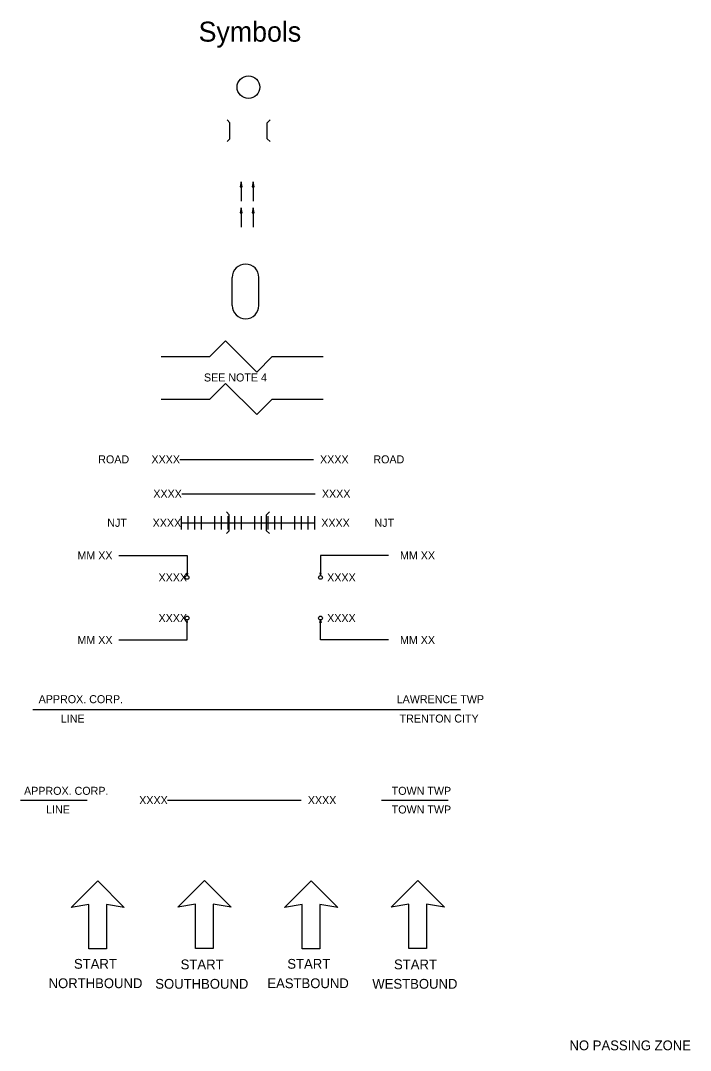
# Model space of a CAD drawing. Extents: x -6359 to 1641, y 3001 to 24737.
# Drawn here: x -4123 to 900, y 3001 to 10724 of the extents above; entities that cross this region are included whole.
import ezdxf

# ---------------------------------------------------------------- set-up
doc = ezdxf.new("R2010")
doc.units = 0
doc.layers.add('_Notes', color=7, linetype='Continuous')

msp = doc.modelspace()

# ---------------------------------------------------------------- linework, layer by layer
at = {"layer": '_Notes'}
for p, q in [((-2553.2, 9957.4), (-2574.4, 9978.6)), ((-2273.2, 9957.4), (-2252, 9978.6)), ((-2553.2, 9837.4), (-2553.2, 9957.4)), ((-2273.2, 9837.4), (-2273.2, 9957.4)), ((-2574.4, 9816.1), (-2553.2, 9837.4)), ((-2252, 9816.1), (-2273.2, 9837.4)), ((-2469.7, 9515.4), (-2469.7, 9370.5)), ((-2379, 9515.4), (-2379, 9370.5)), ((-2469.7, 9319.3), (-2469.7, 9174.4)), ((-2379, 9319.3), (-2379, 9174.4)), ((-2536, 8587.7), (-2536, 8797.7)), ((-2336, 8587.7), (-2336, 8797.7)), ((-2703.4, 8205.1), (-2586.6, 8321.9)), ((-2586.6, 8321.9), (-2352.8, 8088.2)), ((-3068.9, 8205.1), (-2703.4, 8205.1)), ((-2352.8, 8088.2), (-2235.8, 8205.1)), ((-2235.8, 8205.1), (-1853.9, 8205.1)), ((-2703.4, 7885.7), (-2586.6, 8002.5)), ((-2586.6, 8002.5), (-2352.8, 7768.8)), ((-3068.9, 7885.7), (-2703.4, 7885.7)), ((-2352.8, 7768.8), (-2235.8, 7885.7)), ((-2235.8, 7885.7), (-1853.9, 7885.7)), ((-2928.6, 7433.2), (-2428.2, 7433.2)), ((-2428.2, 7433.2), (-1927.7, 7433.2)), ((-2914.6, 7175.7), (-2414.2, 7175.7)), ((-2414.2, 7175.7), (-1913.7, 7175.7)), ((-2559.1, 7017.3), (-2580.3, 7038.5)), ((-2279.1, 7017.3), (-2257.8, 7038.5)), ((-2919.5, 7007.1), (-2919.5, 6907.1)), ((-2919.5, 6957.1), (-2419.1, 6957.3)), ((-2869.5, 7007.1), (-2869.5, 6907.1)), ((-2819.5, 7007.1), (-2819.5, 6907.1)), ((-2769.5, 7007.1), (-2769.5, 6907.1)), ((-2669.5, 7007.1), (-2669.5, 6907.1)), ((-2619.5, 7007.1), (-2619.5, 6907.1)), ((-2569.5, 7007.1), (-2569.5, 6907.1)), ((-2559.1, 6897.3), (-2559.1, 7017.3)), ((-2519.5, 7007.1), (-2519.5, 6907.1)), ((-2469.5, 7007.1), (-2469.5, 6907.1)), ((-2419.1, 6957.3), (-1918.6, 6957.3)), ((-2369.1, 7007.3), (-2369.1, 6907.3)), ((-2319.1, 7007.3), (-2319.1, 6907.3)), ((-2279.1, 6897.3), (-2279.1, 7017.3)), ((-2269.1, 7007.3), (-2269.1, 6907.3)), ((-2219.1, 7007.3), (-2219.1, 6907.3)), ((-2169.1, 7007.3), (-2169.1, 6907.3)), ((-2069.1, 7007.3), (-2069.1, 6907.3)), ((-2019.1, 7007.3), (-2019.1, 6907.3)), ((-1969.1, 7007.3), (-1969.1, 6907.3)), ((-1919.1, 7007.3), (-1919.1, 6907.3)), ((-2580.3, 6876.1), (-2559.1, 6897.3)), ((-2257.8, 6876.1), (-2279.1, 6897.3)), ((-3386.4, 6712), (-2875.3, 6712)), ((-2875.3, 6712), (-2875.3, 6561.8)), ((-1874.4, 6712), (-1874.4, 6561.8)), ((-1363.3, 6712), (-1874.4, 6712)), ((-2875.3, 6079.3), (-2875.3, 6229.4)), ((-1874.4, 6079.3), (-1874.4, 6229.4)), ((-3386.4, 6079.3), (-2875.3, 6079.3)), ((-1363.3, 6079.3), (-1874.4, 6079.3)), ((-4031.2, 5556.5), (-3531.2, 5556.5)), ((-3531.2, 5556.5), (-1324.5, 5556.5)), ((-1324.5, 5556.5), (-824.5, 5556.5)), ((-4123.3, 4877.6), (-3623.3, 4877.6)), ((-3020.4, 4877.6), (-2519.9, 4877.6)), ((-2519.9, 4877.6), (-2019.4, 4877.6)), ((-1416.5, 4877.6), (-916.5, 4877.6)), ((-3744.3, 4072), (-3544.8, 4271.5)), ((-3544.8, 4271.5), (-3345.4, 4072)), ((-2944.3, 4076.3), (-2744.8, 4275.8)), ((-2744.8, 4275.8), (-2545.4, 4076.3)), ((-2144.3, 4072), (-1944.8, 4271.5)), ((-1944.8, 4271.5), (-1745.4, 4072)), ((-1344.3, 4076.3), (-1144.8, 4275.8)), ((-1144.8, 4275.8), (-945.4, 4076.3)), ((-3611.3, 4094.2), (-3744.3, 4072)), ((-3611.3, 3761.7), (-3611.3, 4094.2)), ((-3345.4, 4072), (-3478.3, 4094.2)), ((-3478.3, 4094.2), (-3478.3, 3761.7)), ((-2811.3, 4098.5), (-2944.3, 4076.3)), ((-2811.3, 3766), (-2811.3, 4098.5)), ((-2545.4, 4076.3), (-2678.3, 4098.5)), ((-2678.3, 4098.5), (-2678.3, 3766)), ((-2011.3, 4094.2), (-2144.3, 4072)), ((-2011.3, 3761.7), (-2011.3, 4094.2)), ((-1745.4, 4072), (-1878.3, 4094.2)), ((-1878.3, 4094.2), (-1878.3, 3761.7)), ((-1211.3, 4098.5), (-1344.3, 4076.3)), ((-1211.3, 3766), (-1211.3, 4098.5)), ((-945.4, 4076.3), (-1078.3, 4098.5)), ((-1078.3, 4098.5), (-1078.3, 3766)), ((-3478.3, 3761.7), (-3611.3, 3761.7)), ((-2678.3, 3766), (-2811.3, 3766)), ((-1878.3, 3761.7), (-2011.3, 3761.7)), ((-1078.3, 3766), (-1211.3, 3766))]:
    msp.add_line(p, q, dxfattribs=at)
for points in [[(-2461.7, 9477), (-2469.7, 9515.4), (-2477.7, 9477)], [(-2371, 9477), (-2379, 9515.4), (-2387, 9477)], [(-2461.7, 9280.9), (-2469.7, 9319.3), (-2477.7, 9280.9)], [(-2371, 9280.9), (-2379, 9319.3), (-2387, 9280.9)], [(-2871.3, 6581), (-2875.3, 6561.8), (-2879.3, 6581)], [(-1878.4, 6581), (-1874.4, 6561.8), (-1870.4, 6581)], [(-2871.3, 6210.2), (-2875.3, 6229.4), (-2879.3, 6210.2)], [(-1878.4, 6210.2), (-1874.4, 6229.4), (-1870.4, 6210.2)]]:
    msp.add_lwpolyline(points, close=True, dxfattribs=at)
for centre, radius in [((-2414.3, 10224.4), 85.4), ((-2875.3, 6547.8), 14.1), ((-1874.4, 6547.8), 14.1), ((-2875.3, 6243.5), 14.1), ((-1874.4, 6243.5), 14.1)]:
    msp.add_circle(centre, radius, dxfattribs=at)
for centre, start, end in [((-2436, 8797.7), 90, 180), ((-2436, 8797.7), 0, 90), ((-2436, 8587.7), 180, 270), ((-2436, 8587.7), 270, 0)]:
    msp.add_arc(centre, 100, start, end, dxfattribs=at)

# ---------------------------------------------------------------- texts
for s, height, p in [('Symbols', 150, (-2788.2, 10565.6)), ('SEE NOTE 4 ', 60, (-2748.4, 8017.2)), ('ROAD', 60, (-3541, 7403.2)), ('XXXX', 60, (-3142.1, 7403.2)), ('XXXX', 60, (-1877.7, 7403.2)), ('ROAD', 60, (-1477.7, 7403.2)), ('XXXX', 60, (-3128.1, 7145.7)), ('XXXX', 60, (-1863.7, 7145.7)), ('NJT', 60, (-3473.3, 6927.3)), ('XXXX', 60, (-3133, 6927.3)), ('XXXX', 60, (-1868.6, 6927.3)), ('NJT', 60, (-1469.1, 6927.3)), ('MM XX', 60, (-3697, 6682.6)), ('MM XX', 60, (-1278.3, 6682.6)), ('XXXX', 60, (-3088.8, 6517.8)), ('XXXX', 60, (-1824.4, 6517.8)), ('XXXX', 60, (-3088.8, 6213.5)), ('XXXX', 60, (-1824.4, 6213.5)), ('MM XX', 60, (-3697, 6048.7)), ('MM XX', 60, (-1278.3, 6048.7)), ('APPROX. CORP.', 60, (-3987.8, 5604.9)), ('LAWRENCE TWP', 60, (-1302.9, 5604.9)), ('LINE', 60, (-3821.7, 5459.8)), ('TRENTON CITY', 60, (-1281.2, 5459.8)), ('APPROX. CORP.', 60, (-4097.5, 4917.6)), ('TOWN TWP', 60, (-1340.2, 4917.6)), ('XXXX', 60, (-3233.8, 4847.6)), ('XXXX', 60, (-1969.4, 4847.6)), ('LINE', 60, (-3931.9, 4777.6)), ('TOWN TWP', 60, (-1340.2, 4777.6)), ('NO PASSING ZONE', 73.42, (-7.2, 3002))]:
    msp.add_text(s, height=height, dxfattribs=at).set_placement(p)
for s, p in [('START', (-3723.1, 3613.4)), ('START', (-2923.1, 3609.1)), ('START', (-2123.1, 3613.4)), ('START', (-1323.1, 3609.1)), ('NORTHBOUND', (-3913.4, 3467.8)), ('SOUTHBOUND', (-3113.4, 3463.5)), ('EASTBOUND', (-2273, 3467.8)), ('WESTBOUND', (-1485.6, 3463.5))]:
    msp.add_text(s, height=73.42, rotation=360, dxfattribs=at).set_placement(p)

doc.saveas('drawing.dxf')
